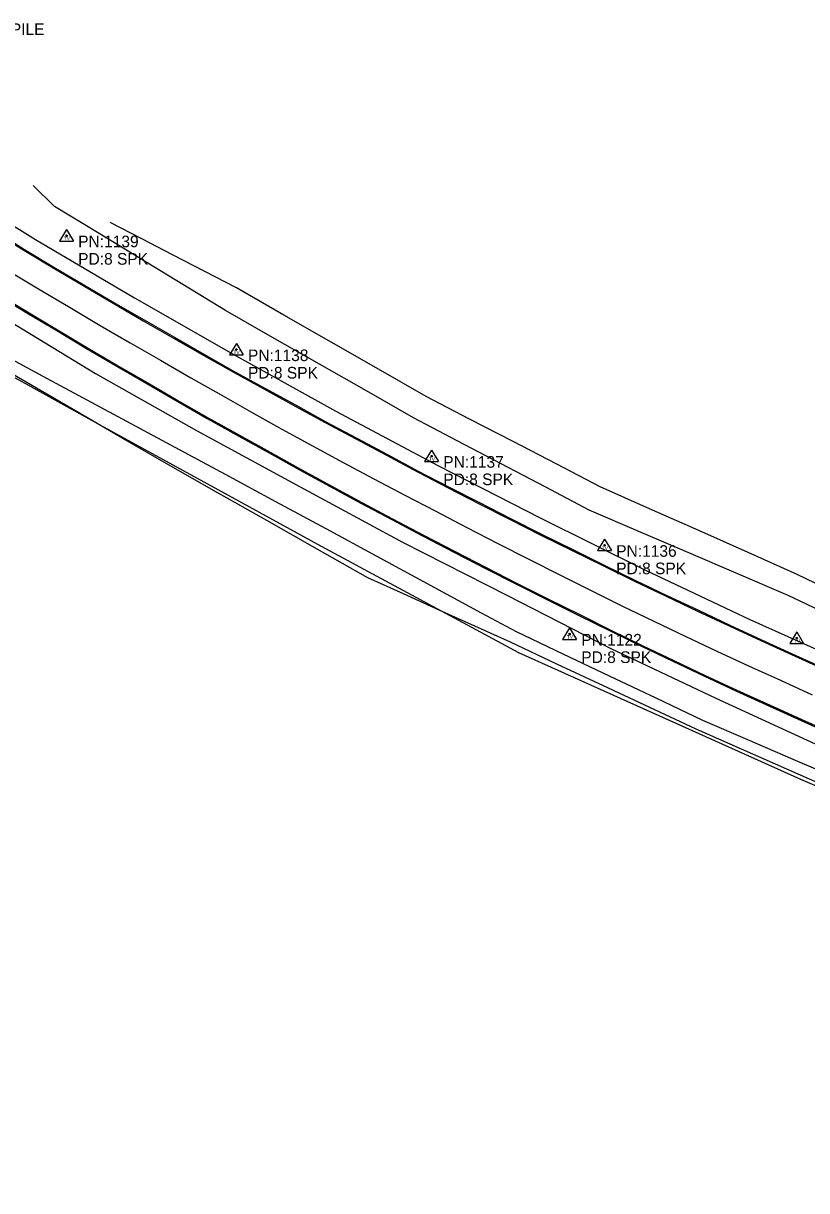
# Model space of a CAD drawing. Extents: x 878399 to 889864, y 1564003 to 1567413.
# Drawn here: x 885515 to 885852, y 1564499 to 1565001 of the extents above; entities that cross this region are included whole.
import ezdxf

# ---------------------------------------------------------------- set-up
doc = ezdxf.new("R2010")
doc.units = 0
for name, color, linetype in [('S_DITCHLINE', 7, 'Continuous'), ('S_EDGE_PAVEMENT', 7, 'Continuous'), ('S_FIBER_OPTIC_CABLE', 7, 'Continuous'), ('S_PAVEMENT_CROWN', 7, 'Continuous'), ('S_SECONDARY_CTL', 7, 'Continuous'), ('S_SECONDARY_CTL_ANNOT', 7, 'Continuous'), ('S_SHOULDER', 7, 'Continuous'), ('S_SURVEY_TEXT_ANNOT', 7, 'Continuous'), ('S_UTL_PT_SYM', 7, 'Continuous')]:
    doc.layers.add(name, color=color, linetype=linetype)

msp = doc.modelspace()

# ---------------------------------------------------------------- linework, layer by layer
at = {"layer": 'S_DITCHLINE'}
for points in [[(885862.87, 1564745.69), (885843.63, 1564754.86), (885822.2, 1564764.04), (885800.78, 1564773.22), (885779.35, 1564782.39), (885757.93, 1564791.57), (885739.02, 1564801.5), (885720.12, 1564811.44), (885701.22, 1564821.37), (885682.31, 1564831.3), (885662.1, 1564842.83), (885641.9, 1564854.36), (885621.69, 1564865.89), (885601.48, 1564877.42), (885583.11, 1564888.62), (885564.74, 1564899.83), (885546.37, 1564911.04), (885527.99, 1564922.24), (885518.7, 1564931.25)], [(885866.86, 1564754.51), (885847.49, 1564763.9), (885826.31, 1564773.31), (885805.12, 1564782.73), (885783.94, 1564792.14), (885762.76, 1564801.56), (885744.01, 1564811.29), (885725.26, 1564821.02), (885706.51, 1564830.75), (885687.76, 1564840.49), (885667.37, 1564852.15), (885646.98, 1564863.82), (885626.59, 1564875.48), (885606.21, 1564887.15), (885592.62, 1564894.2), (885579.03, 1564901.25), (885565.44, 1564908.3), (885551.86, 1564915.35)], [(885865.23, 1564675.86), (885845.75, 1564684.26), (885826.28, 1564692.66), (885806.8, 1564701.06), (885786.78, 1564710.57), (885766.76, 1564720.09), (885746.75, 1564729.6), (885726.73, 1564739.12), (885711.66, 1564747.27), (885696.59, 1564755.42), (885681.53, 1564763.57), (885666.46, 1564771.72), (885644.82, 1564783.43), (885623.18, 1564795.14), (885601.54, 1564806.85), (885579.91, 1564818.56), (885560.95, 1564828.74), (885542, 1564838.93), (885523.05, 1564849.11), (885504.1, 1564859.3)], [(885862.55, 1564671.47), (885843.04, 1564680.05), (885823.54, 1564688.64), (885804.03, 1564697.22), (885784.06, 1564706.58), (885764.08, 1564715.94), (885744.11, 1564725.3), (885724.14, 1564734.67), (885708.77, 1564741.6), (885693.41, 1564748.54), (885678.04, 1564755.48), (885662.68, 1564762.42), (885640.99, 1564774.72), (885619.3, 1564787.03), (885597.61, 1564799.34), (885575.92, 1564811.64), (885557.32, 1564822.43), (885538.72, 1564833.22), (885520.12, 1564844.02), (885501.51, 1564854.81)]]:
    msp.add_lwpolyline(points, dxfattribs=at)
at = {"layer": 'S_EDGE_PAVEMENT'}
for points in [[(885501.96, 1564911.27), (885514.71, 1564903.36), (885514.71, 1564903.36), (885527.32, 1564895.86), (885540.23, 1564888.23), (885553.14, 1564880.59), (885566.11, 1564873.06), (885579.14, 1564865.61), (885592.16, 1564858.16), (885605.21, 1564850.76), (885618.04, 1564843.71), (885631.19, 1564836.5), (885644.35, 1564829.28), (885657.57, 1564822.19), (885670.8, 1564815.13), (885684.04, 1564808.07), (885697.34, 1564801.13), (885710.39, 1564794.45), (885723.75, 1564787.61), (885737.13, 1564780.83), (885750.59, 1564774.22), (885764.06, 1564767.61), (885777.53, 1564761), (885791.07, 1564754.55), (885804.63, 1564748.11), (885818.18, 1564741.68), (885831.8, 1564735.39), (885844.95, 1564729.45), (885858.63, 1564723.28)], [(885502.33, 1564911.58), (885515.08, 1564903.67), (885515.08, 1564903.67), (885527.69, 1564896.17), (885540.61, 1564888.54), (885553.52, 1564880.9), (885566.49, 1564873.37), (885579.51, 1564865.92), (885592.53, 1564858.47), (885605.58, 1564851.07), (885618.42, 1564844.03), (885631.57, 1564836.81), (885644.72, 1564829.59), (885657.94, 1564822.51), (885671.17, 1564815.45), (885684.41, 1564808.38), (885697.71, 1564801.44), (885710.76, 1564794.76), (885724.12, 1564787.93), (885737.49, 1564781.14), (885750.96, 1564774.54), (885764.43, 1564767.93), (885777.89, 1564761.32), (885791.44, 1564754.87), (885804.99, 1564748.43), (885818.54, 1564742), (885832.16, 1564735.71), (885845.31, 1564729.77), (885858.99, 1564723.6)], [(885502.72, 1564884.47), (885516, 1564876.5), (885528.88, 1564868.8), (885528.88, 1564868.8), (885541.76, 1564861.11), (885554.68, 1564853.5), (885567.66, 1564845.98), (885580.65, 1564838.47), (885593.64, 1564830.97), (885607.17, 1564823.44), (885620.27, 1564816.14), (885633.38, 1564808.84), (885646.57, 1564801.68), (885659.78, 1564794.57), (885672.99, 1564787.47), (885686.25, 1564780.45), (885686.25, 1564780.45), (885700, 1564773.36), (885713.33, 1564766.49), (885726.68, 1564759.63), (885726.68, 1564759.63), (885726.68, 1564759.63), (885740.1, 1564752.94), (885740.1, 1564752.94), (885753.53, 1564746.25), (885753.53, 1564746.25), (885753.53, 1564746.25), (885766.96, 1564739.55), (885766.96, 1564739.55), (885766.96, 1564739.55), (885780.46, 1564733.03), (885793.99, 1564726.55), (885807.53, 1564720.07), (885821.12, 1564713.72), (885821.12, 1564713.72), (885835.48, 1564707.24), (885835.48, 1564707.24), (885835.48, 1564707.24), (885849.15, 1564701.07), (885849.15, 1564701.07), (885862.83, 1564694.91)], [(885503.1, 1564884.78), (885516.37, 1564876.81), (885529.25, 1564869.12), (885529.25, 1564869.12), (885542.13, 1564861.43), (885555.06, 1564853.81), (885568.04, 1564846.3), (885581.02, 1564838.78), (885594.01, 1564831.28), (885607.54, 1564823.75), (885620.65, 1564816.45), (885633.75, 1564809.15), (885646.94, 1564802), (885660.15, 1564794.89), (885673.36, 1564787.78), (885686.62, 1564780.77), (885686.62, 1564780.77), (885700.37, 1564773.68), (885713.7, 1564766.81), (885727.04, 1564759.95), (885727.04, 1564759.95), (885727.04, 1564759.95), (885740.47, 1564753.26), (885740.47, 1564753.26), (885753.89, 1564746.56), (885753.89, 1564746.56), (885753.89, 1564746.56), (885767.32, 1564739.87), (885767.32, 1564739.87), (885767.32, 1564739.87), (885780.83, 1564733.35), (885794.36, 1564726.87), (885807.89, 1564720.39), (885821.48, 1564714.05), (885821.48, 1564714.05), (885835.84, 1564707.56), (885835.84, 1564707.56), (885835.84, 1564707.56), (885849.51, 1564701.39), (885849.51, 1564701.39), (885863.19, 1564695.24)]]:
    msp.add_lwpolyline(points, dxfattribs=at)
at = {"layer": 'S_FIBER_OPTIC_CABLE'}
for p, q in [((885547.89, 1564828.01), (885456.16, 1564878.83)), ((885642.78, 1564775.84), (885547.89, 1564828.01)), ((885727.66, 1564730.18), (885642.78, 1564775.84)), ((885849.03, 1564675.55), (885727.66, 1564730.18)), ((885957.86, 1564628.9), (885849.03, 1564675.55))]:
    msp.add_line(p, q, dxfattribs=at)
at = {"layer": 'S_PAVEMENT_CROWN'}
msp.add_lwpolyline([(885508.85, 1564894.12), (885521.79, 1564886.41), (885521.79, 1564886.41), (885521.79, 1564886.41), (885534.67, 1564878.72), (885547.57, 1564871.07), (885547.57, 1564871.07), (885547.57, 1564871.07), (885560.55, 1564863.54), (885573.53, 1564856.02), (885586.51, 1564848.5), (885599.58, 1564841.13), (885599.58, 1564841.13), (885599.58, 1564841.13), (885612.71, 1564833.77), (885625.8, 1564826.43), (885625.8, 1564826.43), (885638.95, 1564819.21), (885638.95, 1564819.21), (885652.16, 1564812.11), (885652.16, 1564812.11), (885665.37, 1564805.01), (885665.37, 1564805.01), (885678.61, 1564797.94), (885691.93, 1564791.04), (885705.3, 1564784.12), (885718.63, 1564777.22), (885718.63, 1564777.22), (885718.63, 1564777.22), (885732, 1564770.44), (885732, 1564770.44), (885745.39, 1564763.67), (885745.39, 1564763.67), (885745.39, 1564763.67), (885758.78, 1564756.9), (885758.78, 1564756.9), (885772.25, 1564750.28), (885785.76, 1564743.78), (885799.28, 1564737.28), (885812.84, 1564730.84), (885826.48, 1564724.6), (885826.48, 1564724.6), (885826.48, 1564724.6), (885840.21, 1564718.33), (885853.86, 1564712.09)], dxfattribs=at)
at = {"layer": 'S_SECONDARY_CTL'}
for p, q in [((885533.1, 1564912.28), (885530.09, 1564907.33)), ((885533.1, 1564912.28), (885536.05, 1564907.33)), ((885530.09, 1564907.33), (885536.05, 1564907.33)), ((885606.16, 1564863.28), (885603.15, 1564858.33)), ((885606.16, 1564863.28), (885609.11, 1564858.33)), ((885603.15, 1564858.33), (885609.11, 1564858.33)), ((885690.19, 1564817.4), (885687.18, 1564812.44)), ((885690.19, 1564817.4), (885693.14, 1564812.44)), ((885687.18, 1564812.44), (885693.14, 1564812.44)), ((885764.58, 1564779.07), (885761.57, 1564774.12)), ((885764.58, 1564779.07), (885767.53, 1564774.12)), ((885761.57, 1564774.12), (885767.53, 1564774.12)), ((885749.56, 1564740.87), (885746.55, 1564735.92)), ((885749.56, 1564740.87), (885752.51, 1564735.92)), ((885847.28, 1564739.1), (885844.27, 1564734.14)), ((885847.28, 1564739.1), (885850.23, 1564734.14)), ((885746.55, 1564735.92), (885752.51, 1564735.92)), ((885844.27, 1564734.14), (885850.23, 1564734.14))]:
    msp.add_line(p, q, dxfattribs=at)
for centre, radius in [((885533.1, 1564909.67), 0.311), ((885533.1, 1564909.67), 0.183), ((885533.1, 1564909.67), 0.103), ((885606.16, 1564860.67), 0.311), ((885606.16, 1564860.67), 0.183), ((885606.16, 1564860.67), 0.103), ((885690.19, 1564814.79), 0.311), ((885690.19, 1564814.79), 0.183), ((885690.19, 1564814.79), 0.103), ((885764.58, 1564776.46), 0.311), ((885764.58, 1564776.46), 0.183), ((885764.58, 1564776.46), 0.103), ((885749.56, 1564738.26), 0.311), ((885749.56, 1564738.26), 0.183), ((885749.56, 1564738.26), 0.103), ((885847.28, 1564736.49), 0.311), ((885847.28, 1564736.49), 0.183), ((885847.28, 1564736.49), 0.103)]:
    msp.add_circle(centre, radius, dxfattribs=at)
at = {"layer": 'S_SHOULDER'}
for points in [[(885477.34, 1564934.42), (885519.82, 1564908.04), (885562.37, 1564882.88), (885605.78, 1564858.06), (885649.01, 1564834.13), (885693.1, 1564810.55), (885737.12, 1564788.02), (885781.98, 1564765.92), (885827.15, 1564744.48), (885871.93, 1564724.36), (885917.84, 1564704.55), (885964.25, 1564685.89), (886009.9, 1564668.12), (886056.86, 1564650.94), (886104.07, 1564634.45), (886150.87, 1564618.86), (886198.78, 1564604.53), (886245.81, 1564590.69), (886294.03, 1564577.4), (886342.52, 1564565.18), (886391.29, 1564554.1), (886439.19, 1564543.9), (886488.35, 1564534.77)], [(885502.12, 1564876.69), (885545.5, 1564850.36), (885589.04, 1564825.78), (885633.6, 1564801.51), (885677.62, 1564777.79), (885722.81, 1564754.83), (885767.3, 1564732.01), (885812.49, 1564710.58), (885858.95, 1564689.25), (885905.17, 1564670.16), (885951.57, 1564651.51), (885999.47, 1564633.52), (886046.46, 1564616.42), (886093.66, 1564599.92), (886142, 1564584.31), (886189.76, 1564569.49), (886238.85, 1564555.08), (886286.99, 1564541.47), (886335.49, 1564529.28), (886384.19, 1564517.92), (886434.5, 1564507.62), (886483.69, 1564498.68)]]:
    msp.add_lwpolyline(points, dxfattribs=at)
at = {"layer": 'S_UTL_PT_SYM'}
for points in [[(885547.89, 1564828.01), (885547.89, 1564828.06), (885547.89, 1564828.01), (885547.84, 1564828.01), (885547.89, 1564828.01), (885547.89, 1564827.96), (885547.89, 1564828.01), (885547.94, 1564828.01)], [(885642.78, 1564775.84), (885642.78, 1564775.89), (885642.78, 1564775.84), (885642.73, 1564775.84), (885642.78, 1564775.84), (885642.78, 1564775.79), (885642.78, 1564775.84), (885642.83, 1564775.84)], [(885727.66, 1564730.18), (885727.66, 1564730.23), (885727.66, 1564730.18), (885727.61, 1564730.18), (885727.66, 1564730.18), (885727.66, 1564730.13), (885727.66, 1564730.18), (885727.71, 1564730.18)], [(885849.03, 1564675.55), (885849.03, 1564675.6), (885849.03, 1564675.55), (885848.98, 1564675.55), (885849.03, 1564675.55), (885849.03, 1564675.5), (885849.03, 1564675.55), (885849.08, 1564675.55)]]:
    msp.add_lwpolyline(points, dxfattribs=at)

# ---------------------------------------------------------------- texts
at = {"layer": 'S_SECONDARY_CTL'}
for p in [(885531.9, 1564907.66), (885604.96, 1564858.66), (885688.99, 1564812.78), (885763.38, 1564774.45), (885748.36, 1564736.25), (885846.07, 1564734.48)]:
    msp.add_text('TV', height=1.5, rotation=360, dxfattribs=at).set_placement(p)
at = {"layer": 'S_SECONDARY_CTL_ANNOT'}
for s, p in [('PN:1139', (885538.1, 1564904.67)), ('PD:8 SPK', (885538.1, 1564897.17)), ('PN:1138', (885611.16, 1564855.67)), ('PD:8 SPK', (885611.16, 1564848.17)), ('PN:1137', (885695.19, 1564809.79)), ('PD:8 SPK', (885695.19, 1564802.29)), ('PN:1136', (885769.58, 1564771.46)), ('PD:8 SPK', (885769.58, 1564763.96)), ('PN:1122', (885754.56, 1564733.26)), ('PD:8 SPK', (885754.56, 1564725.76))]:
    msp.add_text(s, height=5, dxfattribs=at).set_placement(p)
at = {"layer": 'S_SURVEY_TEXT_ANNOT'}
msp.add_text('DIRT PILE', height=5, dxfattribs=at).set_placement((885491.67, 1564996.03))

doc.saveas('drawing.dxf')
